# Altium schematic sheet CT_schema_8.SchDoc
size 251 x 159 mm
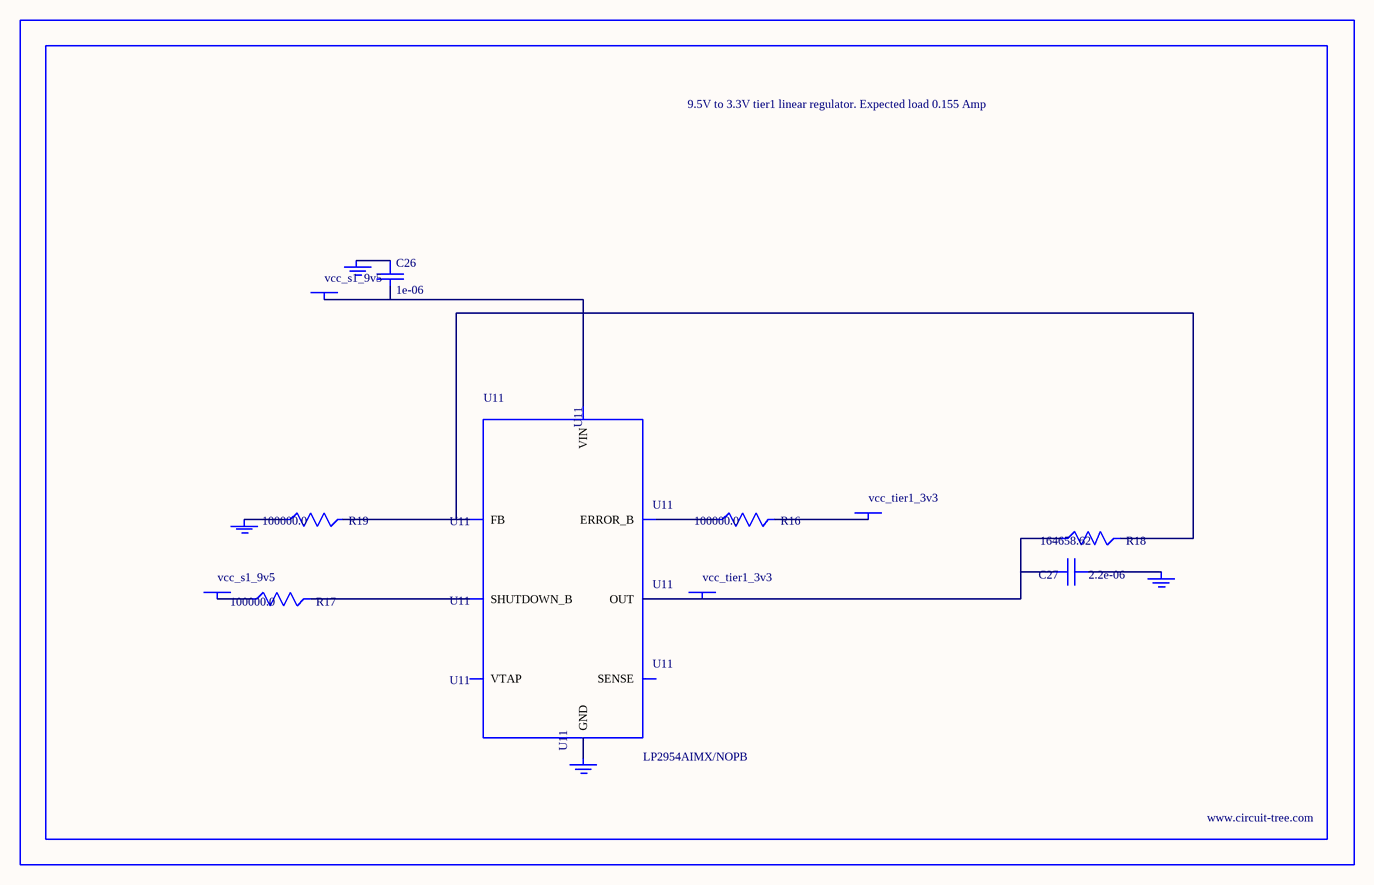
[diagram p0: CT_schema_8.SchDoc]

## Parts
BORDER7  (no value)
C26  1e-06  [EXV-9B]
C27  2.2e-06  [EXV-9B]
GND_INSTANCE_7_0  (no value)
GND_INSTANCE_7_1  (no value)
GND_INSTANCE_7_2  (no value)
GND_INSTANCE_7_3  (no value)
POWER_INSTANCE_7_0  vcc_s1_9v5
POWER_INSTANCE_7_1  vcc_tier1_3v3
POWER_INSTANCE_7_2  vcc_s1_9v5
POWER_INSTANCE_7_3  vcc_tier1_3v3
R16  100000.0  [R0603]
R17  100000.0  [R0603]
R18  164658.62  [R0603]
R19  100000.0  [R0603]
U11  LP2954AIMX/NOPB  [LP2954]

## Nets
NetC26_1: C26.1 GND_INSTANCE_7_2.0(GND)
NetC26_2: C26.2 POWER_INSTANCE_7_2.0(PWR) U11.8(VIN)
NetC27_1: C27.1 GND_INSTANCE_7_0.0(GND)
NetC27_2: C27.2 POWER_INSTANCE_7_3.0(PWR) R18.1 U11.1(OUT)
NetGND_INSTANCE_7_1_0: GND_INSTANCE_7_1.0(GND) R19.1
NetGND_INSTANCE_7_3_0: GND_INSTANCE_7_3.0(GND) U11.4(GND)
NetPOWER_INSTANCE_7_0_0: POWER_INSTANCE_7_0.0(PWR) R17.1
NetPOWER_INSTANCE_7_1_0: POWER_INSTANCE_7_1.0(PWR) R16.2
NetR16_1: R16.1 U11.5(ERROR_B)
NetR17_2: R17.2 U11.3(SHUTDOWN_B)
NetR18_2: R18.2 R19.2 U11.7(FB)

Not connected (* = marked no-connect by the designer): U11 2(SENSE) 6(VTAP)

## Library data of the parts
BORDER7 = BORDER_PAGE7
C26 = EDK105M050A9BAA
C27 = EDK225M050A9BAA
GND_INSTANCE_7_0-GND_INSTANCE_7_3 = GND
POWER_INSTANCE_7_0-POWER_INSTANCE_7_3 = PWR
R16 R17 R19 = RC0603JR-07100KL
R18 = R18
